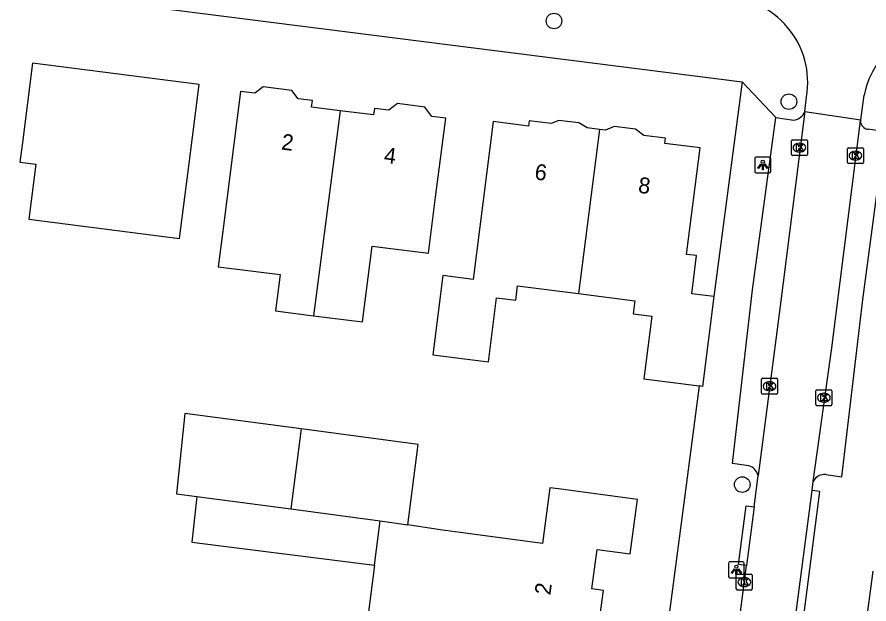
# Model space of a CAD drawing. Extents: x 161696 to 162377, y 380761 to 381673.
# Drawn here: x 161813.9 to 161867.3, y 381279.9 to 381316.7 of the extents above; entities that cross this region are included whole.
import ezdxf

# ---------------------------------------------------------------- set-up
doc = ezdxf.new("R2010")
doc.units = 0
for name, color, linetype in [('IMGEO_Boom', 7, 'Continuous'), ('IMGEO_Kolk', 7, 'Continuous'), ('IMGEO_Lichtpunt', 7, 'Continuous'), ('IMGEO_Muur', 7, 'Continuous'), ('IMGEO_Pand', 7, 'Continuous'), ('IMGEO_Pand_nummerreeks', 7, 'Continuous'), ('IMGEO_Rijbaan_lokaal_open', 7, 'Continuous'), ('IMGEO_Voetpad_open', 7, 'Continuous')]:
    doc.layers.add(name, color=color, linetype=linetype)

msp = doc.modelspace()

# ---------------------------------------------------------------- linework, layer by layer
at = {"layer": 'IMGEO_Boom'}
for centre in [(161847.575, 381316.493), (161862.3, 381311.429), (161859.377, 381287.397)]:
    msp.add_circle(centre, 0.489, dxfattribs=at)
at = {"layer": 'IMGEO_Kolk'}
for p, q in [((161862.46, 381308.117), (161862.46, 381308.969)), ((161862.535, 381309.043), (161863.387, 381309.043)), ((161863.461, 381308.969), (161863.461, 381308.117)), ((161862.948, 381308.823), (161862.973, 381308.823)), ((161865.971, 381307.614), (161865.971, 381308.466)), ((161866.046, 381308.54), (161866.898, 381308.54)), ((161866.972, 381308.466), (161866.972, 381307.614)), ((161863.387, 381308.043), (161862.535, 381308.043)), ((161862.971, 381308.263), (161862.946, 381308.263)), ((161866.459, 381308.32), (161866.484, 381308.32)), ((161866.898, 381307.54), (161866.046, 381307.54)), ((161866.482, 381307.76), (161866.457, 381307.76)), ((161860.586, 381293.14), (161860.586, 381293.992)), ((161860.661, 381294.066), (161861.513, 381294.066)), ((161861.587, 381293.992), (161861.587, 381293.14)), ((161861.074, 381293.846), (161861.099, 381293.846)), ((161861.513, 381293.066), (161860.661, 381293.066)), ((161861.097, 381293.286), (161861.072, 381293.286)), ((161863.992, 381292.422), (161863.992, 381293.274)), ((161864.067, 381293.348), (161864.919, 381293.348)), ((161864.48, 381293.128), (161864.505, 381293.128)), ((161864.993, 381293.274), (161864.993, 381292.422)), ((161864.919, 381292.348), (161864.067, 381292.348)), ((161864.503, 381292.568), (161864.478, 381292.568)), ((161859.004, 381280.848), (161859.004, 381281.7)), ((161859.079, 381281.774), (161859.931, 381281.774)), ((161860.005, 381281.7), (161860.005, 381280.848)), ((161859.492, 381281.554), (161859.517, 381281.554)), ((161859.931, 381280.774), (161859.079, 381280.774)), ((161859.515, 381280.994), (161859.49, 381280.994))]:
    msp.add_line(p, q, dxfattribs=at)
for points in [[(161862.46, 381308.117), (161862.46, 381308.969)], [(161862.535, 381309.043), (161863.387, 381309.043)], [(161863.461, 381308.969), (161863.461, 381308.117)], [(161862.781, 381308.743), (161862.904, 381308.743), (161862.904, 381308.592), (161863.034, 381308.743), (161863.198, 381308.743), (161863.052, 381308.592), (161863.205, 381308.343), (161863.053, 381308.343), (161862.968, 381308.507), (161862.904, 381308.44), (161862.904, 381308.343), (161862.781, 381308.343), (161862.781, 381308.743)], [(161865.971, 381307.614), (161865.971, 381308.466)], [(161866.046, 381308.54), (161866.898, 381308.54)], [(161866.972, 381308.466), (161866.972, 381307.614)], [(161863.387, 381308.043), (161862.535, 381308.043)], [(161866.292, 381308.24), (161866.415, 381308.24), (161866.415, 381308.089), (161866.545, 381308.24), (161866.709, 381308.24), (161866.563, 381308.089), (161866.716, 381307.84), (161866.564, 381307.84), (161866.479, 381308.004), (161866.415, 381307.937), (161866.415, 381307.84), (161866.292, 381307.84), (161866.292, 381308.24)], [(161866.898, 381307.54), (161866.046, 381307.54)], [(161860.586, 381293.14), (161860.586, 381293.992)], [(161860.661, 381294.066), (161861.513, 381294.066)], [(161861.587, 381293.992), (161861.587, 381293.14)], [(161860.907, 381293.766), (161861.03, 381293.766), (161861.03, 381293.615), (161861.16, 381293.766), (161861.324, 381293.766), (161861.178, 381293.615), (161861.331, 381293.366), (161861.179, 381293.366), (161861.094, 381293.53), (161861.03, 381293.463), (161861.03, 381293.366), (161860.907, 381293.366), (161860.907, 381293.766)], [(161861.513, 381293.066), (161860.661, 381293.066)], [(161863.992, 381292.422), (161863.992, 381293.274)], [(161864.067, 381293.348), (161864.919, 381293.348)], [(161864.313, 381293.048), (161864.436, 381293.048), (161864.436, 381292.897), (161864.566, 381293.048), (161864.73, 381293.048), (161864.584, 381292.897), (161864.737, 381292.648), (161864.585, 381292.648), (161864.5, 381292.812), (161864.436, 381292.745), (161864.436, 381292.648), (161864.313, 381292.648), (161864.313, 381293.048)], [(161864.993, 381293.274), (161864.993, 381292.422)], [(161864.919, 381292.348), (161864.067, 381292.348)], [(161859.004, 381280.848), (161859.004, 381281.7)], [(161859.079, 381281.774), (161859.931, 381281.774)], [(161860.005, 381281.7), (161860.005, 381280.848)], [(161859.325, 381281.474), (161859.448, 381281.474), (161859.448, 381281.323), (161859.578, 381281.474), (161859.742, 381281.474), (161859.596, 381281.323), (161859.749, 381281.074), (161859.597, 381281.074), (161859.512, 381281.238), (161859.448, 381281.171), (161859.448, 381281.074), (161859.325, 381281.074), (161859.325, 381281.474)], [(161859.931, 381280.774), (161859.079, 381280.774)]]:
    msp.add_lwpolyline(points, dxfattribs=at)
for centre, start, end in [((161862.537, 381308.967), 91.552, 178.448), ((161862.537, 381308.967), 91.552, 178.448), ((161863.385, 381308.967), 1.552, 88.448), ((161863.385, 381308.967), 1.552, 88.448), ((161866.048, 381308.464), 91.552, 178.448), ((161866.048, 381308.464), 91.552, 178.448), ((161866.896, 381308.464), 1.552, 88.448), ((161866.896, 381308.464), 1.552, 88.448), ((161862.537, 381308.119), 181.552, 268.448), ((161862.537, 381308.119), 181.552, 268.448), ((161863.385, 381308.119), 271.552, 358.448), ((161863.385, 381308.119), 271.552, 358.448), ((161866.048, 381307.616), 181.552, 268.448), ((161866.048, 381307.616), 181.552, 268.448), ((161866.896, 381307.616), 271.552, 358.448), ((161866.896, 381307.616), 271.552, 358.448), ((161860.663, 381293.99), 91.552, 178.448), ((161860.663, 381293.99), 91.552, 178.448), ((161861.511, 381293.99), 1.552, 88.448), ((161861.511, 381293.99), 1.552, 88.448), ((161860.663, 381293.142), 181.552, 268.448), ((161860.663, 381293.142), 181.552, 268.448), ((161861.511, 381293.142), 271.552, 358.448), ((161861.511, 381293.142), 271.552, 358.448), ((161864.069, 381293.272), 91.552, 178.448), ((161864.069, 381293.272), 91.552, 178.448), ((161864.917, 381293.272), 1.552, 88.448), ((161864.917, 381293.272), 1.552, 88.448), ((161864.069, 381292.424), 181.552, 268.448), ((161864.069, 381292.424), 181.552, 268.448), ((161864.917, 381292.424), 271.552, 358.448), ((161864.917, 381292.424), 271.552, 358.448), ((161859.081, 381281.698), 91.552, 178.448), ((161859.081, 381281.698), 91.552, 178.448), ((161859.929, 381281.698), 1.552, 88.448), ((161859.929, 381281.698), 1.552, 88.448), ((161859.081, 381280.85), 181.552, 268.448), ((161859.081, 381280.85), 181.552, 268.448), ((161859.929, 381280.85), 271.552, 358.448), ((161859.929, 381280.85), 271.552, 358.448)]:
    msp.add_arc(centre, 0.0765, start, end, dxfattribs=at)
for centre, major_axis, ratio, start_param, end_param in [((161862.947, 381308.543), (-0.387, 0.002), 0.722429, 4.712389, 7.853982), ((161862.972, 381308.543), (-0.39, 0.002), 0.717154, 1.570796, 4.712389), ((161866.458, 381308.04), (-0.387, 0.002), 0.722429, 4.712389, 7.853982), ((161866.483, 381308.04), (-0.39, 0.002), 0.717154, 1.570796, 4.712389), ((161861.073, 381293.566), (-0.387, 0.002), 0.722429, 4.712389, 7.853982), ((161861.098, 381293.566), (-0.39, 0.002), 0.717154, 1.570796, 4.712389), ((161864.479, 381292.848), (-0.387, 0.002), 0.722429, 4.712389, 7.853982), ((161864.504, 381292.848), (-0.39, 0.002), 0.717154, 1.570796, 4.712389), ((161859.491, 381281.274), (-0.387, 0.002), 0.722429, 4.712389, 7.853982), ((161859.516, 381281.274), (-0.39, 0.002), 0.717154, 1.570796, 4.712389)]:
    msp.add_ellipse(centre, major_axis=major_axis, ratio=ratio, start_param=start_param, end_param=end_param, dxfattribs=at)
at = {"layer": 'IMGEO_Lichtpunt'}
for p, q in [((161860.164, 381307.86), (161860.164, 381307.053)), ((161860.164, 381307.86), (161860.164, 381307.053)), ((161861.066, 381307.955), (161860.258, 381307.955)), ((161861.066, 381307.955), (161860.258, 381307.955)), ((161861.16, 381307.053), (161861.16, 381307.86)), ((161861.16, 381307.053), (161861.16, 381307.86)), ((161860.258, 381306.959), (161861.066, 381306.959)), ((161860.258, 381306.959), (161861.066, 381306.959)), ((161858.508, 381282.449), (161858.508, 381281.642)), ((161858.508, 381282.449), (161858.508, 381281.642)), ((161859.41, 381282.544), (161858.602, 381282.544)), ((161859.41, 381282.544), (161858.602, 381282.544)), ((161859.504, 381281.642), (161859.504, 381282.449)), ((161859.504, 381281.642), (161859.504, 381282.449)), ((161858.602, 381281.548), (161859.41, 381281.548)), ((161858.602, 381281.548), (161859.41, 381281.548))]:
    msp.add_line(p, q, dxfattribs=at)
for points in [[(161860.538, 381307.524), (161860.577, 381307.496), (161860.389, 381307.234), (161860.351, 381307.261), (161860.538, 381307.524)], [(161860.64, 381307.476), (161860.687, 381307.476), (161860.687, 381307.154), (161860.64, 381307.154), (161860.64, 381307.476)], [(161860.75, 381307.496), (161860.788, 381307.523), (161860.975, 381307.261), (161860.936, 381307.233), (161860.75, 381307.496)], [(161858.882, 381282.113), (161858.921, 381282.085), (161858.733, 381281.823), (161858.695, 381281.85), (161858.882, 381282.113)], [(161858.984, 381282.065), (161859.031, 381282.065), (161859.031, 381281.743), (161858.984, 381281.743), (161858.984, 381282.065)], [(161859.094, 381282.085), (161859.132, 381282.112), (161859.319, 381281.85), (161859.28, 381281.822), (161859.094, 381282.085)]]:
    msp.add_lwpolyline(points, dxfattribs=at)
for centre in [(161860.663, 381307.658), (161859.007, 381282.247)]:
    msp.add_circle(centre, 0.0994, dxfattribs=at)
for centre, start, end in [((161860.258, 381307.86), 90, 180), ((161860.258, 381307.86), 90, 180), ((161861.066, 381307.86), 0, 90), ((161861.066, 381307.86), 0, 90), ((161860.258, 381307.053), 180, 270), ((161860.258, 381307.053), 180, 270), ((161861.066, 381307.053), 270, 0), ((161861.066, 381307.053), 270, 360), ((161858.602, 381282.449), 90, 180), ((161858.602, 381282.449), 90, 180), ((161859.41, 381282.449), 0, 90), ((161859.41, 381282.449), 0, 90), ((161858.602, 381281.642), 180, 270), ((161858.602, 381281.642), 180, 270), ((161859.41, 381281.642), 270, 0), ((161859.41, 381281.642), 270, 360)]:
    msp.add_arc(centre, 0.0946, start, end, dxfattribs=at)
at = {"layer": 'IMGEO_Muur'}
msp.add_lwpolyline([(161856.679, 381293.585), (161855.69, 381286.076)], dxfattribs=at)
at = {"layer": 'IMGEO_Pand'}
for points in [[(161824.7, 381307.545), (161825.332, 381312.504), (161814.882, 381313.835), (161814.25, 381308.876), (161814.092, 381307.636), (161815.079, 381307.51), (161814.638, 381304.053), (161824.102, 381302.847), (161824.7, 381307.545)], [(161834.164, 381310.862), (161832.377, 381311.09), (161832.429, 381311.494), (161831.525, 381311.609), (161831.127, 381312.124), (161829.333, 381312.352), (161828.817, 381311.953), (161827.922, 381312.067), (161827.29, 381307.108), (161826.827, 381303.47), (161826.521, 381301.067), (161830.411, 381300.571), (161830.121, 381298.298), (161832.495, 381297.996)], [(161832.495, 381297.996), (161835.573, 381297.604), (161836.18, 381302.368), (161839.704, 381301.92), (161840.152, 381305.438), (161840.784, 381310.397), (161839.921, 381310.507), (161839.471, 381311.088), (161837.761, 381311.306), (161837.221, 381310.888), (161836.314, 381311.003), (161836.262, 381310.595), (161834.164, 381310.862)], [(161834.164, 381310.862), (161832.495, 381297.996)], [(161850.431, 381309.684), (161849.654, 381309.778), (161849.124, 381310.097), (161847.874, 381310.256), (161847.394, 381310.055), (161846.025, 381310.229), (161845.983, 381309.899), (161843.767, 381310.181), (161843.135, 381305.222), (161842.504, 381300.273), (161840.609, 381300.514), (161839.976, 381295.544), (161843.46, 381295.1), (161843.972, 381299.117), (161845.177, 381298.963), (161845.291, 381299.864), (161849.101, 381299.379)], [(161850.431, 381309.684), (161849.101, 381299.379)], [(161857.595, 381299.195), (161856.207, 381299.373), (161856.513, 381301.764), (161855.887, 381301.844), (161856.739, 381308.526), (161854.513, 381308.81), (161854.554, 381309.129), (161853.205, 381309.3), (161852.688, 381309.694), (161851.344, 381309.865), (161850.806, 381309.639), (161850.431, 381309.684)], [(161849.101, 381299.379), (161852.646, 381298.927), (161852.542, 381298.108), (161853.707, 381297.959), (161853.206, 381294.027), (161856.679, 381293.585)], [(161857.595, 381299.195), (161856.876, 381293.56), (161856.679, 381293.585)], [(161831.722, 381290.887), (161824.427, 381291.854), (161823.899, 381286.819), (161825.19, 381286.648)], [(161831.722, 381290.887), (161831.068, 381285.867)], [(161838.404, 381284.864), (161839.053, 381289.915), (161831.722, 381290.887)], [(161850.222, 381277.386), (161850.672, 381280.75), (161849.945, 381280.847), (161850.275, 381283.317), (161852.347, 381283.04), (161852.805, 381286.461), (161847.85, 381287.123), (161847.313, 381287.195), (161846.846, 381283.703), (161842.013, 381284.349), (161840.434, 381284.56), (161838.404, 381284.864)], [(161825.19, 381286.648), (161824.86, 381283.779), (161836.322, 381282.331)], [(161825.19, 381286.648), (161831.068, 381285.867)], [(161831.068, 381285.867), (161836.685, 381285.121)], [(161836.322, 381282.331), (161836.685, 381285.121)], [(161836.685, 381285.121), (161838.404, 381284.864)], [(161836.322, 381282.331), (161835.92, 381279.248)]]:
    msp.add_lwpolyline(points, dxfattribs=at)
at = {"layer": 'IMGEO_Rijbaan_lokaal_open'}
for points in [[(161863.306, 381310.81), (161863.408, 381311.731)], [(161866.801, 381310.288), (161867.011, 381311.834)], [(161863.306, 381310.81), (161861.761, 381298.603), (161860.369, 381287.975)], [(161863.306, 381310.81), (161866.801, 381310.288)], [(161863.824, 381287.593), (161864.987, 381295.988), (161866.793, 381310.228)], [(161866.793, 381310.228), (161866.801, 381310.288)], [(161860.114, 381285.992), (161860.369, 381287.975)], [(161863.751, 381287.017), (161863.824, 381287.593)], [(161862.671, 381278.748), (161863.751, 381287.017)], [(161860.114, 381285.992), (161859.641, 381282.316)], [(161859.161, 381278.6), (161859.641, 381282.316)]]:
    msp.add_lwpolyline(points, dxfattribs=at)
for centre, radius, start, end in [((161858.11, 381312.632), 5.374, 350.3458, 89.7789), ((161872.253, 381310.795), 5.344, 80.9255, 168.7863)]:
    msp.add_arc(centre, radius, start, end, dxfattribs=at)
at = {"layer": 'IMGEO_Voetpad_open'}
for points in [[(161793.381, 381321.065), (161794.522, 381320.92), (161859.366, 381312.667)], [(161859.366, 381312.667), (161857.595, 381299.195)], [(161861.491, 381310.444), (161859.366, 381312.667)], [(161859.797, 381288.563), (161858.769, 381288.718), (161860.014, 381299.613), (161861.491, 381310.444)], [(161861.491, 381310.444), (161862.608, 381310.266)], [(161864.621, 381288.019), (161865.611, 381287.89), (161866.932, 381299.002), (161868.344, 381309.528)], [(161868.344, 381309.528), (161867.278, 381309.693)], [(161856.679, 381293.585), (161855.69, 381286.076), (161851.558, 381254.696)], [(161862.671, 381278.748), (161863.166, 381278.684), (161864.246, 381286.953), (161863.751, 381287.017)], [(161859.641, 381282.316), (161859.145, 381282.378), (161859.618, 381286.054), (161860.114, 381285.992)], [(161867.57, 381281.964), (161863.942, 381254.866)]]:
    msp.add_lwpolyline(points, dxfattribs=at)
for centre, radius, start, end in [((161862.472, 381311.16), 0.904, 278.6254, 337.2381), ((161867.315, 381310.214), 0.523, 178.4991, 265.8882), ((161859.591, 381287.79), 0.8, 13.366, 75.0536), ((161864.518, 381287.254), 0.772, 82.2985, 153.9509)]:
    msp.add_arc(centre, radius, start, end, dxfattribs=at)

# ---------------------------------------------------------------- texts
at = {"layer": 'IMGEO_Pand_nummerreeks'}
for s, rotation, p in [('2', 352.6031, (161830.44, 381308.433)), ('4', 352.6021, (161836.873, 381307.597)), ('6', 352.7293, (161846.322, 381306.549)), ('8', 352.7293, (161852.812, 381305.72)), ('2', 82.3913, (161847.345, 381280.422))]:
    msp.add_text(s, height=1, rotation=rotation, dxfattribs=at).set_placement(p)

doc.saveas('drawing.dxf')
